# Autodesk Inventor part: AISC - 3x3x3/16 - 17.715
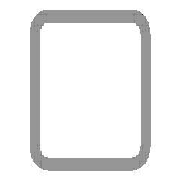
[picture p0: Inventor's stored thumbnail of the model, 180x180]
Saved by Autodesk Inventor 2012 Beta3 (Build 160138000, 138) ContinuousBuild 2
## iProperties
_CCFamilyMember: 9
_CCFamilyDisplayName: ANSI AISC (Square) - Tube
_FrameMemberDoc: Frame Member File
_Version: 15.0.0
_GetPNFromCC: 1
Created: 2011-01
Part Number: AISC - 3x3x3/16 - 17.715
Material: Steel, Mild
Description: Tube
Document SubType Name: Modeling
Standard: ANSI
Designer: Beta-8540w
Standards Organization: ANSI
Language: en-US
Size Designation: 3x3x3/16
Categories: <MemberInstance><Categories><Category DisplayName="Structural Shapes" InternalName="089c4875-fa83-4c05-b084-43b9cc11f5ed" Mnemonic="GRDR"><CategoryParameter Dis
Stock Number: 3x3x3/16
Density: 7.86 g/cm^3
IsCustomPart: 1
G_L: 17.715 in
G_W: 3.000 in
G_H: 3.000 in
Author: Beta-8540w
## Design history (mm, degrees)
node "Start plane"
node "End plane"
sketch "Sketch"
  geometry: L1 (-38.1, -28.575)-(-38.1, 28.575); L2 (-28.575, 38.1)-(28.575, 38.1); L3 (38.1, 28.575)-(38.1, -28.575); L4 (28.575, -38.1)-(-28.575, -38.1); L5 (-28.575, 33.337)-(28.575, 33.338); L6 (33.338, 28.575)-(33.338, -28.575); L7 (28.575, -33.337)-(-28.575, -33.338); L8 (-33.338, -28.575)-(-33.338, 28.575); L9 (0, 56.102)-(0, -56.102) reference; L10 (-56.102, 0)-(56.102, 0) reference; A1 r 9.525 centre (-28.575, -28.575) between (-38.1, -28.575) and (-28.575, -38.1); A2 r 9.525 centre (-28.575, 28.575) between (-28.575, 38.1) and (-38.1, 28.575); A3 r 9.525 centre (28.575, 28.575) between (38.1, 28.575) and (28.575, 38.1); A4 r 9.525 centre (28.575, -28.575) between (28.575, -38.1) and (38.1, -28.575); A5 r 4.763 centre (-28.575, 28.575) between (-28.575, 33.337) and (-33.338, 28.575); A6 r 4.763 centre (28.575, 28.575) between (33.338, 28.575) and (28.575, 33.338); A7 r 4.763 centre (28.575, -28.575) between (28.575, -33.337) and (33.338, -28.575); A8 r 4.763 centre (-28.575, -28.575) between (-33.338, -28.575) and (-28.575, -33.338)
  constraints: 16 end point, 16 point on circle, 8 centre point, 8 tangent, 4 parallel, 3 equal radius, 2 perpendicular, 7 other
  dimensions: "d10" = 76.2 distance between parallel lines of L2 L4 (= G_H); "d11" = 76.2 distance between parallel lines of L1 L3 (= G_W); "d12" = 4.7625 distance between parallel lines of L3 L6 (= G_T); "d15" = 38.1 distance between parallel lines of L2 L10 (= 0.5 x d10); "d16" = 38.1 distance between parallel lines of L9 L3 (= 0.5 x d11); "d17" = 9.525 radius of A1 (= G_IR)
extrude "Body" new body sketch "Sketch" stored distance "d3" = 449.97309 (= G_L); taper "d4" = 0 deg
node "Driven Length"
  sketch "Sketch3"
    geometry: L1 (0, 0)-(10, 0) reference
    constraints: 2 end point, 1 horizontal
  workplane "Work Plane3"
  sketch "Sketch4"
    geometry: L1 (-2, 0)-(12, 0) reference; L2 (-2, 449.973)-(12, 449.973) reference
    dimensions: "d19" = 449.97309 distance between parallel lines of L1 L2 (derived)
body "Solid1"
other parameters: "G_W" = 76.2 [user parameter; used in 1 equation term], "G_H" = 76.2 [user parameter; used in 1 equation term], "G_T" = 4.7625 [user parameter; used in 1 equation term], "G_IR" = 9.525 [user parameter; used in 1 equation term], "G_L" = 449.97309 (= d19) [user parameter; used in 1 equation term], "G_OFFSET_START" = 0 [user parameter; used in 1 equation term], "G_OFFSET_END" = 0 [user parameter; used in 1 equation term], "d13" = 0 (computed from G_OFFSET_START), "d14" = 449.97309 (= G_OFFSET_END + B_L), "B_L" = 449.97309 [user parameter; used in 1 equation term], "d18" = 90 deg
